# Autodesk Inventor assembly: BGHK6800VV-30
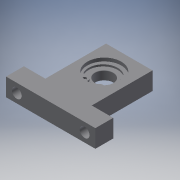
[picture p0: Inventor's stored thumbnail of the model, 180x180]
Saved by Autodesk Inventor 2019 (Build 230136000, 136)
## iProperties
Category: PARTsolutions
Company: MISUMI
Created: 2022-11
Part Number: BGHK6800VV-30
Catalog Web Link: www.cadenas.de
Description: BGHKB, BGHK, BGHKA, BGHKSA, BGHKS-Bearings with Housings T-Shaped h Selectable
Vendor: MISUMI
Document SubType Name: Assembly
Designer: psAdmin
Manufacturer: MISUMI
Mass: 11.7791 g
Surface Area: 63.3194 cm^2
Volume: 11.7791 cm^3
Density: 1 g/cm^3
Title: BGHK6800VV-30
Author: Cadenas PARTsolutions
Comments: Bearings with Housings T-Shaped h Selectable
PSOL_IDENT_0: {$CADENAS_DATA/23d-libs/misumi/metric/12_bearing_holders/bghkb_asmtab.prj},241 {VTYP=3D},{STYP=ASSTA
PSOL_IDENT_1: B},{NB=BGHK6800VV-30},{LINA=BGHK6800VV-30},{NN=BGHKB, BGHK, BGHKA, BGHKSA, BGHKS},{DATE=30.06.2021 1
PSOL_IDENT_2: 2:58:11},{GEOMDATE=09.07.2015 08:06:15},{VERSION=},{LINEID=300},{WBVAR=MATB,MATH,STH,SEAL,HH,ALT1,AL
PSOL_IDENT_3: T2},{WBNUMERIC=HH}  {NB=BGHK6800VV-30},{LINA=BGHK6800VV-30},{KT=DUMMY},{PN=BGHK6800VV-30},{TYPE=BGHK
PSOL_IDENT_4: },{MATB=S},{MATBALG='S','Steel','SS','Stainless Steel'},{MATH=S45C},{MATHALG='S45C','1045 Carbon Ste
PSOL_IDENT_5: el','2017AA','2017 Aluminum Alloy'},{STH=ENP},{STHALG='BO','Black Oxide','ENP','Electroless Nickel P
PSOL_IDENT_6: lating'},{ARR=304 Stainless Steel},{ARR3D=-S},{BN=6800},{SEAL=VV},{SEALALG='ZZ','Double Shielded','V
PSOL_IDENT_7: V','Non-Contact Sealed Rubber Seal','DD','Contact Sealed Rubber Seal'},{HH=30},{HHALG=[20,25,30]},{D
PSOL_IDENT_8: D=10},{D=19},{DD2=20},{MM=1.15},{DDHH=16},{B=5},{LL1=2},{H=44},{H2=14},{L=50},{L1=38.0},{L2=26},{T=1
PSOL_IDENT_9: 0},{S=10},{DD1=5.5},{ALT1=},{ALT2=},{PPATH=bghkb/bghkb_asmtpl.prj}
NB: BGHK6800VV-30
NN: BGHKB, BGHK, BGHKA, BGHKSA, BGHKS
NT: Bearings with Housings T-Shaped h Selectable
NBSYN: $PN.
LINA: BGHK6800VV-30
CATALOG: Misumi
PN: BGHK6800VV-30
MATB: Steel
MATH: 1045 Carbon Steel
STH: Electroless Nickel Plating
ARR: 304 Stainless Steel
BN: 6800
SEAL: Non-Contact Sealed Rubber Seal
HH: 30
DD: 10
D: 19
DDHH: 16
B: 5
LL1: 2
H: 44
L: 50
L1: 38
L2: 26
T: 10
S: 10
DD1: 5.5
ALT1: Bearings, Retaining Rings Assembled
ALT2: w/o KCC (C2 Chamfer)
SUPPLIER: MISUMI
ARTICLENO: BGHK6800VV-30
BOMINFO: BGHK6800VV-30
CREATOR: CADENAS GmbH
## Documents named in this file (4)
- e:\temp\worker_COMMON_12\temp\tmp_7100_138_WfqSE\format_0\BGHK6800VV-30.iam
- e:\temp\worker_COMMON_12\temp\tmp_7100_138_WfqSE\format_0\BGHK6800VV-30_h.ipt
- e:\temp\worker_COMMON_12\temp\tmp_7100_138_WfqSE\format_0\bearing_6800.ipt
- e:\temp\worker_COMMON_12\temp\tmp_7100_138_WfqSE\format_0\RRING-C-INT-S-19.ipt
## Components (3 placed, 3 different names)
1. BGHK6800VV-30_h:1 — to_bearing_XY@1 <-> to_housing_XY@2, to_bearing_Z@1 <-> to_housing_Z@2, to_bearing_YZ@1 <-> to_housing_YZ@2, to_rring_XY@1 <-> rr_XY@3, to_rring_Z@1 <-> rr_Z@3, to_rring_YZ@1 <-> rr_YZ@3
2. bearing_6800:1 — to_bearing_XY@1 <-> to_housing_XY@2, to_bearing_Z@1 <-> to_housing_Z@2, to_bearing_YZ@1 <-> to_housing_YZ@2
3. RRING-C-INT-S-19:1 — to_rring_XY@1 <-> rr_XY@3, to_rring_Z@1 <-> rr_Z@3, to_rring_YZ@1 <-> rr_YZ@3
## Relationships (6: Mate 4, Angle 2)
- to_bearing_XY@1 <-> to_housing_XY@2 [Mate]: BGHK6800VV-30_h:1 ↔ bearing_6800:1
- to_bearing_Z@1 <-> to_housing_Z@2 [Mate]: BGHK6800VV-30_h:1 ↔ bearing_6800:1
- to_bearing_YZ@1 <-> to_housing_YZ@2 [Angle]: BGHK6800VV-30_h:1 ↔ bearing_6800:1
- to_rring_XY@1 <-> rr_XY@3 [Mate]: BGHK6800VV-30_h:1 ↔ RRING-C-INT-S-19:1
- to_rring_Z@1 <-> rr_Z@3 [Mate]: BGHK6800VV-30_h:1 ↔ RRING-C-INT-S-19:1
- to_rring_YZ@1 <-> rr_YZ@3 [Angle]: BGHK6800VV-30_h:1 ↔ RRING-C-INT-S-19:1
